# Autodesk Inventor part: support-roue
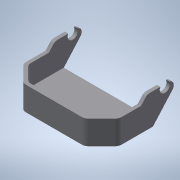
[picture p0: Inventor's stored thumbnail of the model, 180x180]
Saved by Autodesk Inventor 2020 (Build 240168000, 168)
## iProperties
Created: 2021-10
Part Number: support-roue
Material: Générique
Document SubType Name: Modeling
Designer: bruno
Density: 1 g/cm^3
Appearance: Par défaut
Author: bruno
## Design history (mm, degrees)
sketch "Esquisse1"
  geometry: L1 (0, 0)-(7, 0); L2 (7, 0)-(7, 15); L3 (7, 15)-(0, 15); L4 (0, 15)-(0, 0)
  constraints: 8 end point, 2 parallel, 1 horizontal, 1 perpendicular
  dimensions: "d0" = 7 distance of L3.end L2.end; "d1" = 15 distance of L2.end L1.end
extrude "Extrusion1" new body sketch "Esquisse1" distance "d2" = 28; taper "d3" = 0 deg
chamfer "Chanfrein1" distance "d4" = 5; stored, may be unused: second distance "d5" = 2, angle "d6" = 45 deg
sketch "Esquisse2"
  geometry: L1 (-10, 0)-(0, 0) reference; L2 (0, 0)-(5.739, 6.508); L3 (-2.146, 8.492)-(-3.462, 7); L4 (0, 7)-(-10, 7) reference; L5 (2.168, 9)-(-1.021, 9); L6 (-3.462, 7)-(0, 0); A1 r 1.5 centre (4.614, 7.5) between (5.739, 6.508) and (4.819, 8.986); A2 r 1.5 centre (-1.021, 7.5) between (-1.021, 9) and (-2.146, 8.492); A3 r 1.5 centre (3.49, 8.291) between (2.168, 9) and (4.819, 8.986); 1 further point
  constraints: 8 end point, 6 point on circle, 4 tangent, 3 centre point, 2 point on line, 1 equal radius, 1 parallel
  dimensions: "d7" = 12 distance of L1.end point (7.937, 9); "d9" = 1.5 radius of A1; "d14" = 1.5 radius of A3
extrude "Extrusion2" join sketch "Esquisse2" stored distance "d10" = 28; taper "d11" = 0 deg
feature "Coque1" dims "d12" = 1
fillet "Congé1" dims "d13" = 2
node "Solide1"
other parameters: "d8" = 2
